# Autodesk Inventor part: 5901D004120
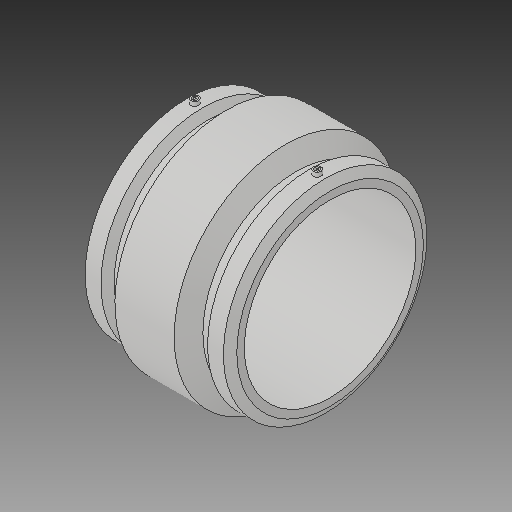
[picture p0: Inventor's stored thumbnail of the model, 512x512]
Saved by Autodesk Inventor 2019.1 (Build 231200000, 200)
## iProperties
Created: 2017-06
Part Number: 5901D004120
Material: Generic
Description: PLASSON COUPLER 12''DIPS
Document SubType Name: Modeling
Designer: KIM
Mass: 96874 g
Surface Area: 34549.7 cm^2
Volume: 96874 cm^3
Density: 1 g/cm^3
Appearance: Default
Author: KIM
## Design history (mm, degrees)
derived "5901D.ipt"
feature "Solid1::5901D.ipt"
tag "TaggingFeature1"
body "Solid1"
other parameters: "d13" = 279.4, "d15" = 137.922, "d16" = 137.922, "d17" = 323.4, "d22" = 399.796, "d23" = 420.624, "d24" = 351.82048, "d25" = 150 deg, "d26" = 111.76, "d27" = 120 deg, "d29" = 199.898, "d35" = 15, "d39" = 0, "d40" = 4, "d41" = 14, "d42" = 0, "d44" = 48.2727, "d45" = 323.4, "d47" = 0, "d48" = 191.90208, "d49" = 48.2727, "d50" = 60 deg, "d57" = 65.786, "d58" = 48.2727, "d62" = 323.4, "d65" = 282.448, "d67" = 5.27613, "d68" = 21.15863, "d69" = 21.80789, "d70" = 21.71015, "d71" = 20.5722, "d72" = 20.71531, "d73" = 561.2638, "d76" = 111.76, "d77" = 351.82048, "d_" = 323.4, "L_" = 279.4, "L_1" = 137.922, "D_" = 420.624, "A_" = 199.898, "A_1" = 25.4, "d60" = 187.96
